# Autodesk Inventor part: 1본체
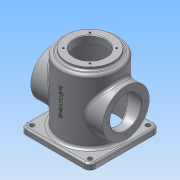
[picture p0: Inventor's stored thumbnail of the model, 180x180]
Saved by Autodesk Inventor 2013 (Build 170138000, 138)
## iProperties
Created: 2015-10
Part Number: 1본체
Material: 알루미늄 6061
Document SubType Name: Modeling
Designer: Administrator
Mass: 985.996 g
Surface Area: 1037.34 cm^2
Volume: 363.836 cm^3
Density: 2.71 g/cm^3
Author: Administrator
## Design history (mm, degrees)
sketch "스케치1"
  geometry: L1 (-50, 60)-(50, 60); L2 (60, 50)-(60, -50); L3 (50, -60)-(-50, -60); L4 (-60, -50)-(-60, 50); A1 r 10 centre (-50, 50) between (-50, 60) and (-60, 50); A2 r 10 centre (50, 50) between (60, 50) and (50, 60); A3 r 10 centre (50, -50) between (50, -60) and (60, -50); A4 r 10 centre (-50, -50) between (-60, -50) and (-50, -60); 5 further points
  constraints: 8 end point, 8 point on circle, 8 tangent, 4 centre point, 4 point on line, 3 equal radius, 2 midpoint, 2 parallel, 2 perpendicular, 1 horizontal, 1 horizontal alignment, 1 vertical alignment
  dimensions: "d0" = 120 distance of point (60, 60) point (60, -60); "d2" = 10 radius of A1
extrude "돌출1" new body sketch "스케치1" distance "d3" = 10; taper "d4" = 0 deg
sketch "스케치2"
  geometry: L1 (0, 0)-(0, 136.29); L2 (0, 125)-(-40, 125); L3 (-40, 125)-(-40, 120); L4 (-40, 120)-(-50, 120); L5 (-50, 120)-(-50, 10); L6 (50, 10)-(-50, 10) reference; L7 (-50, 10)-(0, 10); L8 (0, 10)-(0, 125)
  constraints: 14 end point, 3 perpendicular, 2 parallel, 2 point on line, 1 midpoint, 1 vertical
  dimensions: "d5" = 125 distance from line of L2 L1.start; "d6" = 110 distance between parallel lines of L4 L6; "d7" = 80 diameter of L3 L1; "d8" = 100 diameter of L5 L1
revolve "회전1" sketch "스케치2" stored, may be unused: angle "d9" = 90 deg
sketch "스케치3"
  geometry: C1 r 40 at (0, 60); 1 further point
  constraints: 1 centre point, 1 vertical alignment
  dimensions: "d10" = 60 distance of C1.centre point (0, 0); "d11" = 80 diameter of C1
extrude "돌출2" join sketch "스케치3" stored distance "d12" = 124; taper "d13" = 0 deg
sketch "스케치5"
  geometry: L1 (-3.602, 45.113)-(-3.602, 94.887); L2 (-3.602, 94.887)-(3.602, 94.887); L3 (3.602, 94.887)-(3.602, 45.113); L4 (3.602, 45.113)-(-3.602, 45.113); 4 further points
  constraints: 2 midpoint, 2 vertical alignment, 1 horizontal alignment, 1 vertical, 2 other
  dimensions: "d34" = 70 distance of point (0, 70) point (0, 0); "d35" = 7.20489 distance between parallel lines of L3 L1; "d36" = 49.77477 distance between parallel lines of L2 L4
feature "엠보싱1" sketch "스케치5" dims "d0" = 120, "d2" = 10, "d8" = 100, "d37" = 0.5, "d38" = 0
sketch "스케치4"
  geometry: L1 (-27, 125)-(-27, 112); L2 (-27, 112)-(-45, 112); L3 (-45, 112)-(-45, 0); L4 (40, 125)-(-40, 125) reference; L5 (-27, 125)-(0, 125); L6 (0, -5.017)-(0, 139.964); L7 (-45, 0)-(0, 0); L8 (0, 125)-(0, 0)
  constraints: 14 end point, 2 collinear, 2 perpendicular, 1 horizontal alignment, 1 midpoint, 1 parallel, 1 point on line
  dimensions: "d16" = 13 distance between parallel lines of L2 L4; "d22" = 54 diameter of L1 L6; "d23" = 90 diameter of L3 L6
revolve "회전2" sketch "스케치4" stored, may be unused: angle "d24" = 90 deg
hole "구멍1" diameter "d27" = 54; stored, may be unused: countersink angle "d31" = 90 deg, drill point angle "d33" = 118 deg; dims "d25" = 10, "d26" = 10, "d28" = 6, "d29" = 4, "d30" = 2, "d32" = 8
sketch "스케치6"
  geometry: A1 r 32.5 centre (0, 0) between (-22.981, 22.981) and (22.981, 22.981); 3 further points
  constraints: 4 point on circle, 2 horizontal alignment, 2 vertical alignment, 1 centre point, 1 coincident
  dimensions: "d39" = 65 diameter of A1; "d41" = 90 deg dimension on point (0, 0) A1.end A1.start
hole "구멍2" sketch "스케치6" at (-22.981, 22.981), (22.981, 22.981), (22.981, -22.981), (-22.981, -22.981) diameter "d43" = 3.242; stored, may be unused: countersink angle "d47" = 90 deg, drill point angle "d49" = 118 deg; dims "d44" = 8, "d45" = 4, "d46" = 2, "d48" = 10
sketch "스케치7"
  geometry: 2 further points
  constraints: 1 horizontal alignment
  dimensions: "d50" = 92.5 distance of point (32.5, 0) point (-60, 0)
hole "구멍3" sketch "스케치7" at (32.5, 0) diameter "d51" = 3.242; stored, may be unused: countersink angle "d55" = 90 deg, drill point angle "d57" = 118 deg; dims "d52" = 8, "d53" = 4, "d54" = 2, "d56" = 10
hole "구멍4" diameter "d63" = 8; stored, may be unused: countersink angle "d67" = 90 deg, drill point angle "d69" = 118 deg; dims "d61" = 10, "d62" = 10, "d64" = 8, "d65" = 4, "d66" = 2, "d68" = 10
hole "구멍5" diameter "d72" = 8; stored, may be unused: countersink angle "d76" = 90 deg, drill point angle "d78" = 118 deg; dims "d70" = 10, "d71" = 10, "d73" = 8, "d74" = 4, "d75" = 2, "d77" = 10
hole "구멍6" diameter "d81" = 8; stored, may be unused: countersink angle "d85" = 90 deg, drill point angle "d87" = 118 deg; dims "d79" = 10, "d80" = 10, "d82" = 8, "d83" = 4, "d84" = 2, "d86" = 10
hole "구멍7" diameter "d90" = 8; stored, may be unused: countersink angle "d94" = 90 deg, drill point angle "d96" = 118 deg; dims "d88" = 10, "d89" = 10, "d91" = 8, "d92" = 4, "d93" = 2, "d95" = 10
chamfer "모따기1" distance "d97" = 1; stored, may be unused: second distance "d98" = 2, angle "d99" = 45 deg
chamfer "모따기2" distance "d100" = 3; stored, may be unused: second distance "d101" = 2, angle "d102" = 45 deg
fillet "모깎기1" dims "d103" = 3
fillet "모깎기2" dims "d104" = 5
fillet "모깎기3" dims "d105" = 3
node "솔리드1"
pattern_circular "원형 패턴1" dims angle "d59" = 360 deg
mirror "대칭1"
